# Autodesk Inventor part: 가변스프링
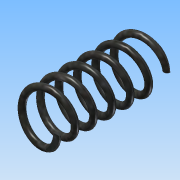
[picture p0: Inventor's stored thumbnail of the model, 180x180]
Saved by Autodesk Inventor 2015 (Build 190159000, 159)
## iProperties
Created: 2020-02
Part Number: 가변스프링
Material: 강철
Document SubType Name: Modeling
Designer: user
Density: 7.85 g/cm^3
Appearance: 플레이트
Mass: 6.43026 g
Surface Area: 16.6219 cm^2
Volume: 0.819142 cm^3
Author: user
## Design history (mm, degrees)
sketch "스케치1"
  geometry: L1 (0, 0)-(7, 0); L2 (7, 0)-(7, 35.5); L3 (7, 35.5)-(0, 35.5); L4 (0, 35.5)-(0, 0); C1 r 1 at (7, 0)
  constraints: 8 end point, 2 parallel, 1 centre point, 1 coincident, 1 horizontal, 1 perpendicular
  dimensions: "d0" = 7 distance of L1.start L1.end; "d1" = 2 diameter of C1; "d2" = 35.5 distance of L1.end L2.end (derived)
feature "코일1" sketch "스케치1" pitch "d3" = 10; turns "d5" = 6; dims "d4" = 35.5 (= d2), "d6" = 0, angle "d7" = 90 deg, angle "d8" = 90 deg, "d9" = 0, "d10" = 0
node "작업 평면1"
feature "분할1"
feature "분할2"
node "솔리드1"
